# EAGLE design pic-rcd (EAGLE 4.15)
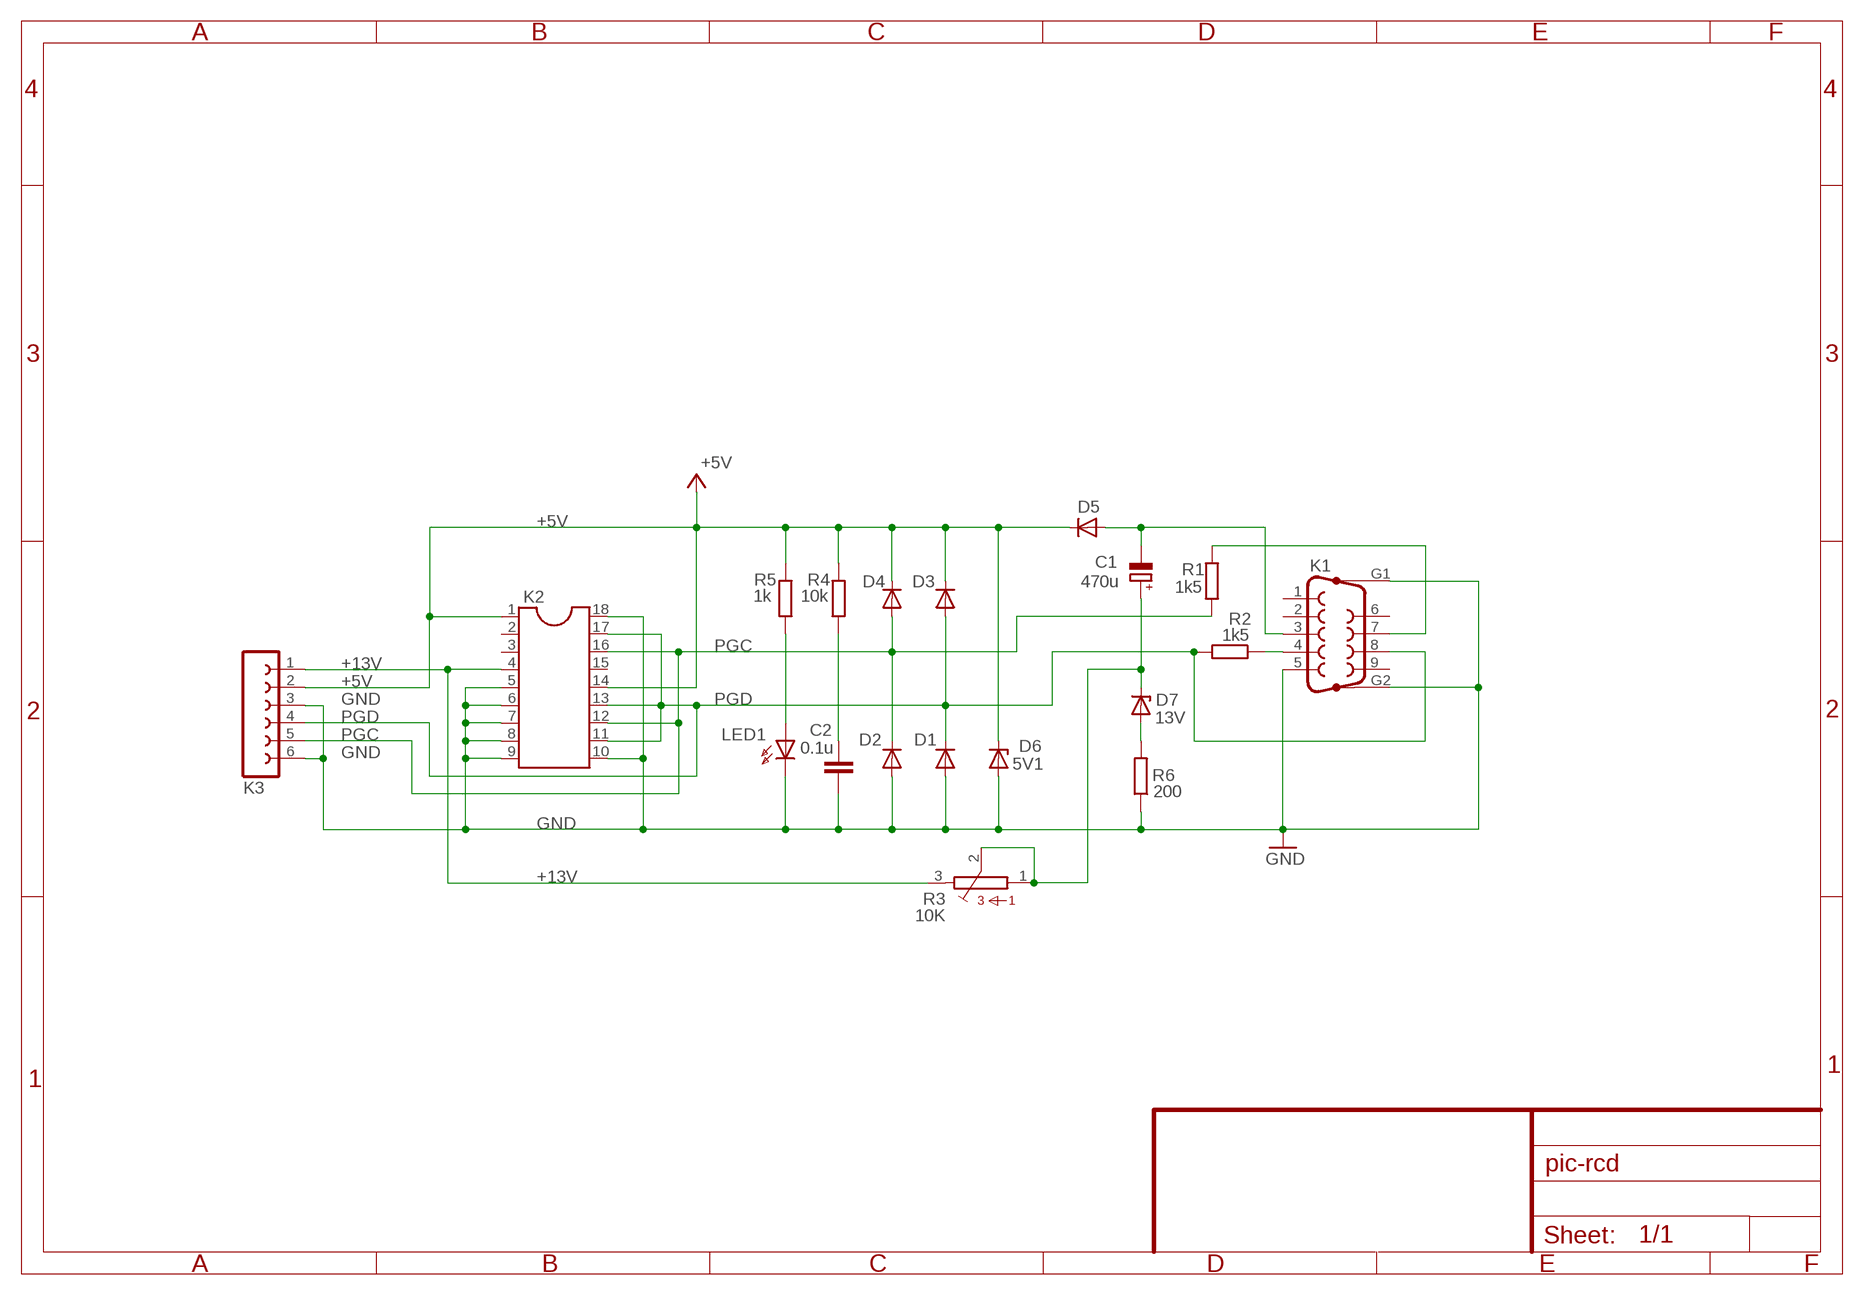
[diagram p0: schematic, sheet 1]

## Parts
C1  470u  CPOL-EUE2.5-6  [E2,5-6]
C2  0.1u  C-EU025_050-035X075  [C025_050-035X075]
D1  DIODE-D-5  [D-5]
D2  DIODE-D-5  [D-5]
D3  DIODE-D-5  [D-5]
D4  DIODE-D-5  [D-5]
D5  DIODE-D-5  [D-5]
D6  5V1  ZENER-DIODEZD-5  [ZDIO-5]
D7  13V  ZENER-DIODEZD-5  [ZDIO-5]
K1  F09HP  [F09HP]
K2  DIL18  [DIL18]
K3  FE06-1  [FE06]
LED1  LED3MM  [LED3MM]
R1  1k5  R-EU_0204/7  [0204/7]
R2  1k5  R-EU_0204/7  [0204/7]
R3  10K  B64W  [B64W]
R4  10k  R-EU_0204/7  [0204/7]
R5  1k  R-EU_0204/7  [0204/7]
R6  200  R-EU_0204/7  [0204/7]

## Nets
+5V: D3.C D4.C D5.C D6.C K2.1 K2.14 K3.2 R4.2 R5.2
+13V: K2.4 K3.1 R3.3
GND: C2.2 D1.A D2.A D6.A K1.5 K1.G1 K1.G2 K2.5 K2.6 K2.7 K2.8 K2.9 K2.10 K2.18 K3.3 K3.6 LED1.K(C) R6.1
N$1: D7.A R6.2
N$2: C1.+ D7.C R3.1 R3.2
N$3: LED1.A R5.1
N$4: C2.1 R4.1
N$9: C1.- D5.A K1.3
N$10: K1.4 R2.1
N$11: K1.7 R1.1
PGC: D2.C D4.A K2.12 K2.16 K3.5 R1.2
PGD: D1.C D3.A K1.8 K2.11 K2.13 K2.17 K3.4 R2.2
Unconnected: K1.1 K1.2 K1.6 K1.9 K2.2 K2.3 K2.15

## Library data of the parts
C1 = rcl:CPOL-EU: POLARIZED CAPACITOR, European symbol
C2 = rcl:C-EU: CAPACITOR, European symbol
D1-D5 = diode:DIODE-: DIODE
D6 D7 = diode:ZENER-DIODE: Z-Diode
K1 = con-subd:F09HP: HARTING SUB-D
K2 = dil:DIL18: SOCKET DIL18
K3 = con-lsta:FE06-1: FEMALE HEADER
LED1 = led:LED3MM: LED
R1 R2 R4-R6 = rcl:R-EU_: RESISTOR, European symbol
R3 = pot:B64W: POTENTIOMETER

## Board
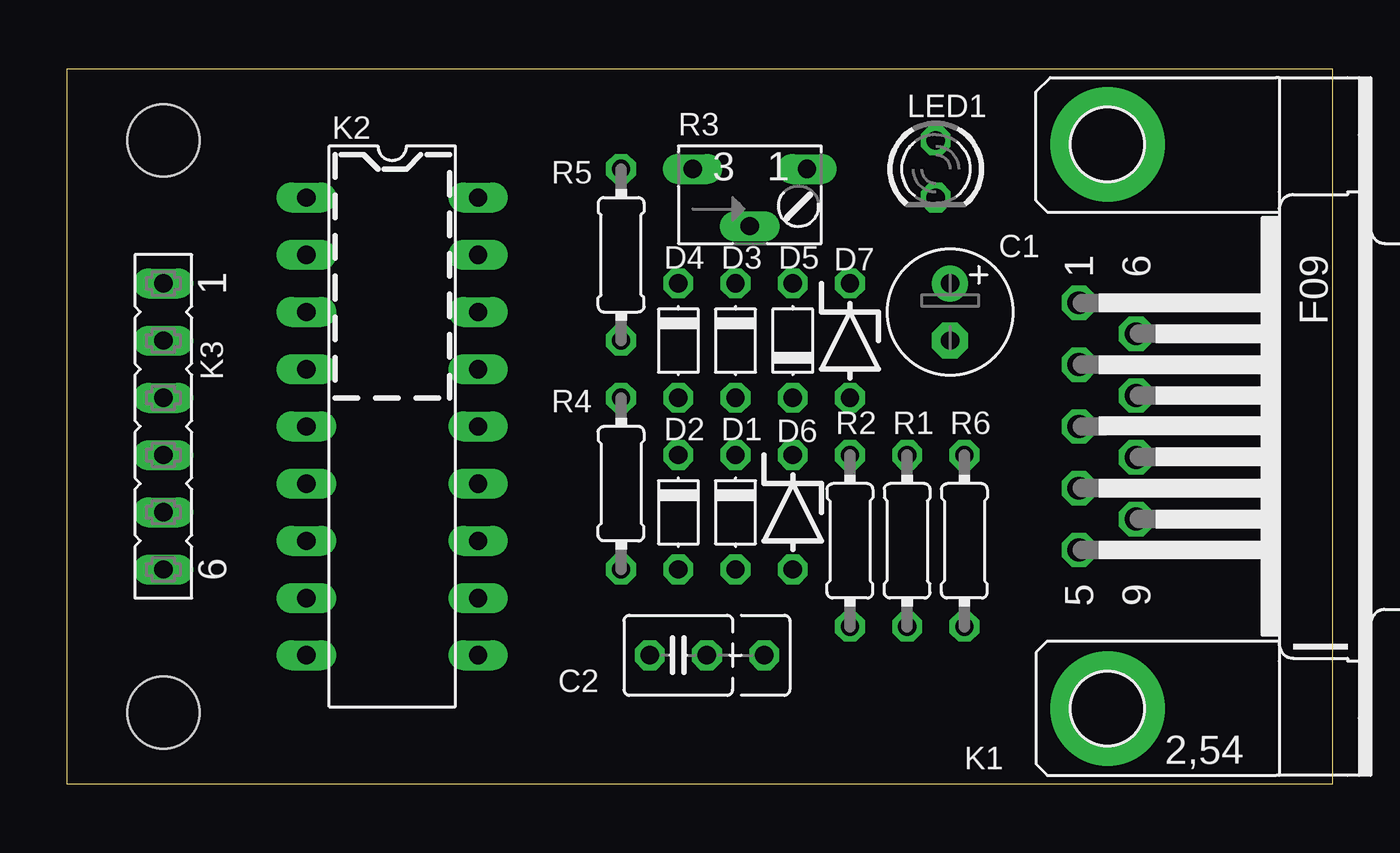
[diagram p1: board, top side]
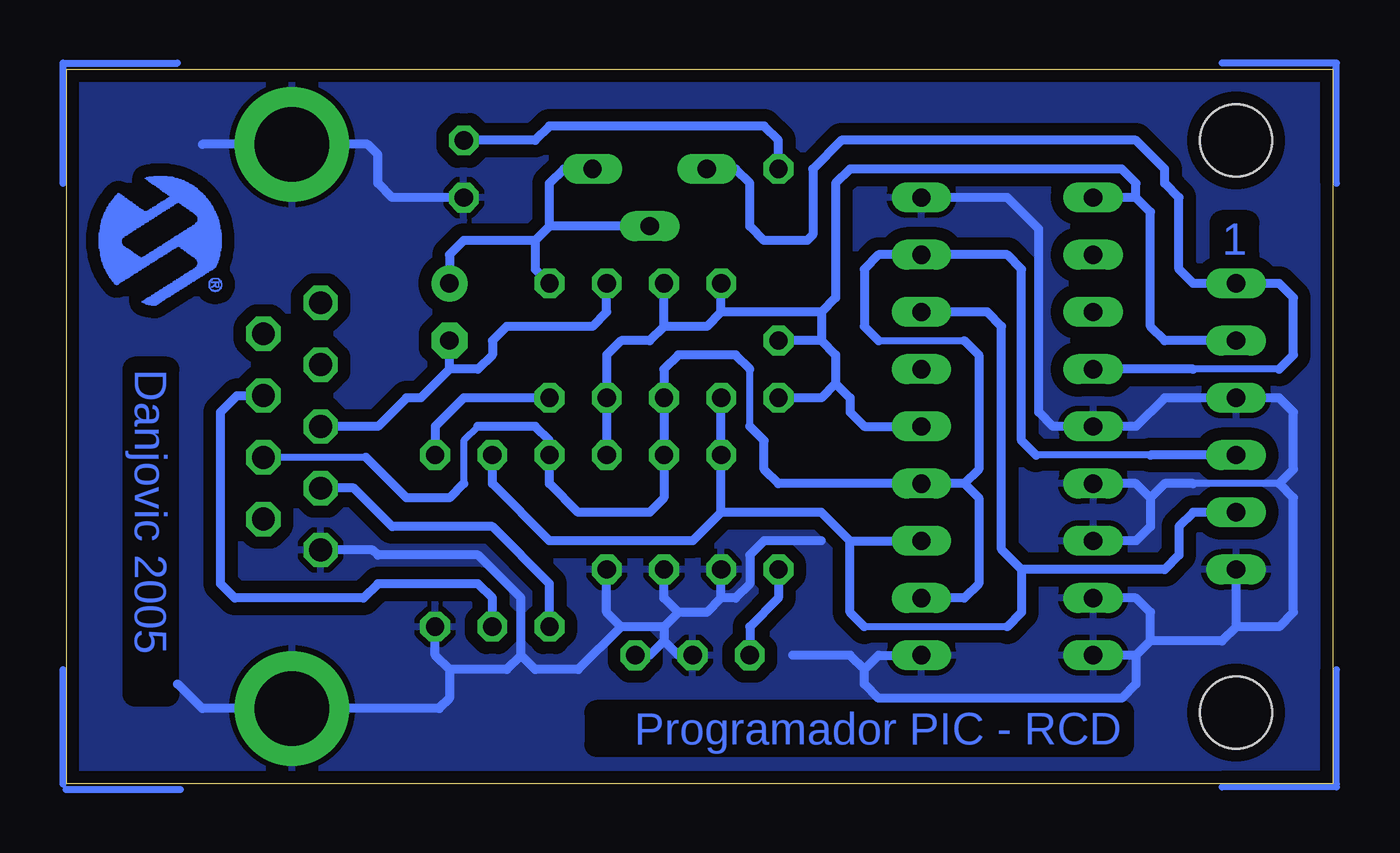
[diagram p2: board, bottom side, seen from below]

Size 56.19 x 31.74 mm. Coordinates in mm from the lower left corner, seen from the top.
Outline: 0,0 56.19,0 56.19,31.74 0,31.74 0,0
Copper layers (1*16): Top 0.035mm / dielectric 1.5mm / Bottom 0.035mm
Design rules "default": minimum track width 10mil, minimum drill 24mil, track to track 22mil, track to pad 22mil, pad to pad 22mil, via to via 22mil, smd to smd 8mil, copper to edge 22mil, drill to drill 8mil, minimum pad ring 10mil, minimum via ring 8mil, stop-mask expansion 4mil, vias tented up to drill 0mil, thermal gap 10mil
Holes 3.2 mm at 4.28,3.17 4.28,28.57

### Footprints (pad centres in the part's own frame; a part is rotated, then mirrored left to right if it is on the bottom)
E2,5-6 = drill 0.813 pad 1.6 round: + -1.27,0 | drill 0.813 pad 1.6 octagon: - 1.27,0
C025_050-035X075 = drill 0.813 octagon: 1 -1.27,0; 2 1.27,0; 3 3.81,0
D-5 = drill 0.813 octagon: A 2.54,0; C -2.54,0
ZDIO-5 = drill 0.813 octagon: A 2.54,0; C -2.54,0
F09HP = drill 1.016 octagon: 1 -5.486,-1.27; 2 -2.743,-1.27; 3 0,-1.27; 4 2.743,-1.27; 5 5.486,-1.27; 6 -4.115,1.27; 7 -1.372,1.27; 8 1.372,1.27; 9 4.115,1.27 | drill 3.302 pad 5.08 round: G1 -12.522,0; G2 12.522,0
DIL18 = drill 0.813 long: 1 -10.16,-3.81; 2 -7.62,-3.81; 3 -5.08,-3.81; 4 -2.54,-3.81; 5 0,-3.81; 6 2.54,-3.81; 7 5.08,-3.81; 8 7.62,-3.81; 9 10.16,-3.81; 10 10.16,3.81; 11 7.62,3.81; 12 5.08,3.81; 13 2.54,3.81; 14 0,3.81; 15 -2.54,3.81; 16 -5.08,3.81; 17 -7.62,3.81; 18 -10.16,3.81
FE06 = drill 0.813 long: 1 -6.35,0; 2 -3.81,0; 3 -1.27,0; 4 1.27,0; 5 3.81,0; 6 6.35,0
LED3MM = drill 0.813 octagon: A -1.27,0; K 1.27,0
0204/7 = drill 0.813 octagon: 1 -3.81,0; 2 3.81,0
B64W = drill 0.813 long: 1 2.54,0; 2 0,-2.54; 3 -2.54,0

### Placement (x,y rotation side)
C1  39.2,20.95 270 top
C2  27.14,5.71 0 top
D1  29.68,12.06 270 top
D2  27.14,12.06 270 top
D3  29.68,19.68 270 top
D4  27.14,19.68 270 top
D5  32.22,19.68 90 top
D6  32.22,12.06 270 top
D7  34.76,19.68 270 top
K1  46.19,15.87 270 top
K2  14.44,15.87 270 top
K3  4.28,15.87 270 top
LED1  38.57,27.3 270 top
R1  37.3,10.79 90 top
R2  34.76,10.79 90 top
R3  30.31,27.3 0 top
R4  24.6,13.33 90 top
R5  24.6,23.49 270 top
R6  39.84,10.79 90 top

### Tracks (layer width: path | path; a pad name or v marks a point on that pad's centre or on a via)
+5V
  Bottom 0.406: D6.C D5.C 32.22,19.04 31.58,19.68 30.31,19.68 29.68,20.31 | 27.14,20.95 D4.C | 29.68,20.31 D3.C | 29.68,20.31 27.77,20.31 27.14,20.95 | 8.73,26.03 K2.1 | K3.2 7.46,19.68 8.09,20.31 8.09,25.39 8.73,26.03 | 8.73,26.03 8.73,26.66 9.36,27.3 21.42,27.3 22.06,26.66 22.06,21.58 22.7,20.95 | 22.7,20.95 22.7,19.68 | 22.7,19.68 R5.2 | 22.7,20.95 27.14,20.95 | 22.7,19.68 22.06,19.04 22.06,17.77 | 22.06,17.77 22.7,17.14 R4.2 | K2.14 20.79,15.87 21.42,16.5 21.42,17.14 22.06,17.77
+13V
  Bottom 0.305: 2.38,18.41 6.18,18.41
  Bottom 0.406: 6.18,18.41 K2.4 | 2.38,18.41 1.74,19.04 1.74,21.58 2.38,22.22 K3.1 6.18,22.22 6.82,22.86 6.82,26.03 7.46,26.66 7.46,27.3 8.73,28.57 21.81,28.57 23.08,27.3 23.08,24.38 23.33,24.12 25.23,24.12 25.87,24.76 25.87,26.66 26.5,27.3 R3.3
GND
  Bottom 0.305: 2.38,13.33 6.18,13.33
  Bottom 0.406: 27.14,8.25 D2.A | R6.1 39.84,5.71 39.2,5.08 | 36.03,5.71 35.39,5.08 33.49,5.08 31.58,6.98 | 36.03,5.71 36.66,5.08 39.2,5.08 | C2.2 29.04,5.71 29.68,6.34 | 29.68,6.34 30.31,5.71 30.95,5.71 | 29.04,7.62 29.68,6.98 | 29.68,6.98 29.68,6.34 | 27.14,8.25 27.77,7.62 29.04,7.62 | D1.A 29.68,8.25 29.04,7.62 | D6.A 32.22,7.62 31.58,6.98 | 29.68,6.98 31.58,6.98 | 23.96,5.71 21.42,5.71 20.79,5.08 | 22.7,10.79 25.23,10.79 25.87,10.16 25.87,8.89 26.5,8.25 27.14,8.25 | K1.5 42.61,10.38 42.38,10.16 37.94,10.16 36.03,8.25 36.03,5.71 | 4.28,6.98 2.38,6.98 1.74,7.62 1.74,12.7 2.38,13.33 1.74,13.97 1.74,16.5 2.38,17.14 K3.3 7.46,17.14 8.73,15.87 K2.5 12.41,15.87 13.04,16.5 13.04,24.63 14.44,26.03 K2.18 | 4.28,6.98 4.92,6.34 8.09,6.34 | 8.09,6.34 8.73,5.71 | 8.09,12.7 8.73,13.33 K2.6 | 8.73,5.71 K2.9 | 4.28,6.98 K3.6 | 51.27,4.44 50.18,3.35 K1.G2 39.66,3.35 39.2,3.8 39.2,5.08 | 50.18,28.39 K1.G1 42.84,28.39 42.38,27.93 42.38,26.66 41.74,26.03 LED1.K | 20.79,5.08 20.15,5.71 K2.10 | 20.79,5.08 20.79,4.44 20.15,3.8 9.36,3.8 8.73,4.44 8.73,5.71 | 8.09,12.7 8.09,11.43 8.73,10.79 K2.7 | 6.18,13.33 7.46,13.33 8.09,12.7 | K2.8 8.73,8.25 8.09,7.62 8.09,6.34
  pour Bottom: -0.8,32.38 -0.8,-0.64 58.25,-0.64 58.25,32.38
N$1
  Bottom 0.406: D7.A 38.57,17.14 39.84,15.87 R6.2
N$2
  Bottom 0.406: R3.1 34.12,27.3 34.76,26.66 34.76,24.76 | R3.2 34.76,24.76 | 34.76,24.76 35.39,24.12 | 35.39,24.12 35.39,22.86 D7.C | C1.+ 39.2,23.49 38.57,24.12 35.39,24.12
N$3
  Bottom 0.406: R5.1 24.6,28.57 25.23,29.2 34.76,29.2 35.39,28.57 LED1.A
N$4
  Bottom 0.406: R4.1 24.6,8.25 25.87,6.98 C2.1
N$6
  Bottom 0.305: 51.27,32 56.35,32 56.35,26.66
N$7
  Bottom 0.305: 4.92,32 -0.17,32 -0.17,26.66
N$8
  Bottom 0.305: 56.35,-0.01 56.35,5.08
N$9
  Bottom 0.406: D5.A 32.22,20.95 32.85,20.31 36.66,20.31 37.3,19.68 37.3,19.04 37.94,18.41 39.2,18.41 | 39.2,18.41 40.48,17.14 41.11,17.14 42.38,15.87 K1.3 | 39.2,18.41 C1.-
N$10
  Bottom 0.406: K1.4 43.45,13.13 41.74,11.43 37.3,11.43 34.76,8.89 R2.1
N$11
  Bottom 0.406: K1.7 48.63,17.24 49.37,16.5 49.37,8.89 48.73,8.25 43.02,8.25 42.38,8.89 37.94,8.89 37.3,8.25 R1.1
N$12
  Bottom 0.305: -0.17,-0.01 -0.17,5.08
N$13
  Bottom 0.305: -0.17,-0.13 4.92,-0.13
N$14
  Bottom 0.305: 51.14,-0.26 56.22,-0.26
PGC
  Bottom 0.305: 14.44,6.98 20.79,6.98
  Bottom 0.406: R1.2 37.3,13.33 34.76,10.79 28.41,10.79 27.14,12.06 | 27.14,12.06 D2.C D4.A | 21.42,10.79 K2.12 | 21.42,10.79 22.7,12.06 27.14,12.06 | K2.16 15.33,20.95 14.69,20.31 14.69,10.41 13.81,9.52 | 13.81,9.52 13.81,7.62 14.44,6.98 | 20.79,6.98 21.42,7.62 21.42,10.79 | K3.5 6.18,12.06 6.82,11.43 6.82,10.16 7.46,9.52 13.81,9.52
PGD
  Bottom 0.305: 25.87,15.87 25.87,18.41 | 37.94,15.87 38.57,15.24 38.57,13.33 | 42.91,14.5 K1.8 | 20.15,19.68 16.34,19.68 | 8.09,14.6 13.17,14.6
  Bottom 0.406: 25.87,15.87 25.23,15.24 25.23,13.97 24.6,13.33 K2.13 16.34,13.33 | 25.87,18.41 26.5,19.04 29.04,19.04 29.68,18.41 D3.A D1.C 29.68,12.7 30.31,12.06 33.49,12.06 34.76,13.33 R2.2 34.76,15.24 35.39,15.87 37.94,15.87 | 38.57,13.33 39.2,12.7 41.11,12.7 42.91,14.5 | 20.15,19.68 20.79,20.31 20.79,22.86 20.15,23.49 K2.17 14.44,23.49 13.81,22.86 13.81,15.24 13.17,14.6 | K2.11 16.34,8.25 15.71,8.89 15.71,12.7 16.34,13.33 | 16.34,19.68 15.71,19.04 15.71,13.97 16.34,13.33 | K3.4 8.09,14.6
(copper drawn outside any net)
  shapes: Bottom area x518

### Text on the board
Bottom: 1 | Danjovic 2005 | Programador PIC - RCD
tDocu: MCLR (13V) | VDD (+5V) | PIC 12 | GND | PGD | PGC | PGM | Programador PIC - RCD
